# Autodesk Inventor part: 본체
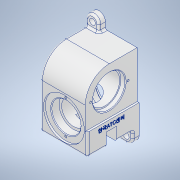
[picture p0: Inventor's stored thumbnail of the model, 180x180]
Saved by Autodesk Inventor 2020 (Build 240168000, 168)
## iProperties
Created: 2023-09
Part Number: 본체
Material: 알루미늄 6061
Document SubType Name: Modeling
Designer: oem
Density: 2.6997 g/cm^3
Appearance: 알루미늄 - 평지
Mass: 944 g
Surface Area: 630.599 cm^2
Volume: 349.669 cm^3
Author: oem
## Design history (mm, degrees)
sketch "스케치1"
  geometry: L1 (-40, 53)-(40, 53); L2 (40, 53)-(40, -53); L3 (40, -53)-(-40, -53); L4 (-40, -53)-(-40, 53); L5 (-40, 53)-(40, -53); L6 (40, 53)-(-40, -53); 1 further point
  constraints: 12 end point, 2 midpoint, 2 parallel, 1 horizontal, 1 perpendicular
  dimensions: "d0" = 80 distance of L1.start L1.end; "d1" = 106 distance of L1.end L2.end
extrude "돌출1" new body sketch "스케치1" stored distance "d2" = 72; taper "d3" = 0 deg
sketch "스케치2"
  geometry: L1 (-40, 53)-(-40, -53) reference; L2 (40, 53)-(-40, 53) reference; C1 r 37 at (-3, 16); 3 further points
  constraints: 2 tangent, 1 centre point
  dimensions: "d4" = 74 diameter of C1
extrude "돌출2" cut sketch "스케치2" stored distance "d5" = 72; taper "d6" = 0 deg
sketch "스케치3"
  geometry: L1 (72, 0)-(0, 0) reference; L2 (72, 0)-(0, 0) reference; L3 (0, -20)-(72, -20); L4 (72, -20)-(72, 0); L5 (72, 0)-(0, 0); L6 (0, 0)-(0, -20); L7 (0, -20)-(72, 0); L8 (72, -20)-(0, 0); 4 further points
  constraints: 12 end point, 3 midpoint, 2 parallel, 1 horizontal, 1 perpendicular, 1 vertical alignment
  dimensions: "d7" = 20 distance of L5.end L3.start
extrude "돌출3" join sketch "스케치3" distance "d8" = 10; taper "d9" = 0 deg
sketch "스케치4"
  geometry: L1 (72, 0)-(0, 0) reference; L2 (52, 20)-(72, 20); L3 (72, 20)-(72, 0); L4 (72, 0)-(52, 0); L5 (52, 0)-(52, 20); L6 (52, 20)-(72, 0); L7 (72, 20)-(52, 0); 3 further points
  constraints: 12 end point, 2 midpoint, 2 parallel, 1 horizontal, 1 perpendicular
  dimensions: "d11" = 20 distance of L2.end L1.start; "d12" = 20 distance of L2.start L2.end
extrude "돌출4" join sketch "스케치4" distance "d13" = 10; taper "d14" = 0 deg
sketch "스케치10"
  geometry: L1 (72, 69)-(72, 0) reference; L2 (72, 106)-(72, -20) reference; L3 (72, 106)-(69, 106); L4 (69, 106)-(69, 34); L5 (69, 34)-(72, 34); L6 (72, 34)-(72, 106); 2 further points
  constraints: 8 end point, 2 parallel, 1 horizontal, 1 perpendicular
  dimensions: "d29" = 72 distance of L3.end L4.end; "d30" = 3 distance of L2.start L3.end
extrude "돌출9" cut sketch "스케치10" stored distance "d31" = 4; taper "d32" = 0 deg
sketch "스케치11"
  geometry: C1 r 25 at (37, 35); A1 r 37 centre (37, 35) between (37, 72) and (0, 35) reference; 1 further point
  constraints: 1 centre point, 1 coincident
  dimensions: "d33" = 50 diameter of C1
extrude "돌출10" cut sketch "스케치11" distance "d34" = 7; taper "d35" = 0 deg
sketch "스케치12"
  geometry: C1 r 25 at (0, 0) reference; C2 r 23 at (0, 0); 1 further point
  constraints: 1 centre point, 1 coincident
  dimensions: "d36" = 46 diameter of C2
extrude "돌출11" cut sketch "스케치12" distance "d37" = 40; taper "d38" = 0 deg
sketch "스케치13"
  geometry: C1 r 23 at (0, 0) reference; C2 r 17.5 at (0, 0); 1 further point
  constraints: 1 centre point, 1 coincident
  dimensions: "d39" = 35 diameter of C2
extrude "돌출12" cut sketch "스케치13" distance "d40" = 15; taper "d41" = 0 deg
sketch "스케치14"
  geometry: C1 r 17.5 at (0, 0) reference; C2 r 15.5 at (0, 0); 1 further point
  constraints: 1 centre point, 1 coincident
  dimensions: "d42" = 31 diameter of C2
extrude "돌출13" cut sketch "스케치14" distance "d43" = 4; taper "d44" = 0 deg
sketch "스케치15"
  geometry: L1 (0, -20)-(72, -20) reference; C1 r 31.5 at (36, 35); 1 further point
  constraints: 1 centre point, 1 vertical alignment
  dimensions: "d45" = 55 distance from line of L1 C1.centre; "d46" = 63 diameter of C1
extrude "돌출14" cut sketch "스케치15" distance "d47" = 3; taper "d48" = 0 deg
sketch "스케치16"
  geometry: C1 r 31.5 at (0, 0) reference; C2 r 22.5 at (0, 0); 1 further point
  constraints: 1 centre point, 1 coincident
  dimensions: "d49" = 45 diameter of C2
extrude "돌출15" cut sketch "스케치16" distance "d50" = 12; taper "d51" = 0 deg
sketch "스케치17"
  geometry: C1 r 31.5 at (36, 55) reference; C2 r 22.5 at (36, 55) reference; C3 r 31.5 at (36, 55); 1 further point
  constraints: 1 centre point, 1 coincident
  dimensions: "d52" = 63 diameter of C3
extrude "돌출16" cut sketch "스케치17" distance "d53" = 8; taper "d54" = 0 deg
sketch "스케치18"
  geometry: C1 r 31.5 at (0, 0) reference; C2 r 22.5 at (0, 0); 1 further point
  constraints: 1 centre point, 1 coincident
  dimensions: "d55" = 45 diameter of C2
extrude "돌출17" cut sketch "스케치18" distance "d56" = 12; taper "d57" = 0 deg
sketch "스케치19"
  geometry: C1 r 22.5 at (0, 0) reference; C2 r 18.5 at (0, 0); 1 further point
  constraints: 1 centre point, 1 coincident
  dimensions: "d58" = 37 diameter of C2
extrude "돌출18" cut sketch "스케치19" stored distance "d59" = 12; taper "d60" = 0 deg
sketch "스케치20"
  geometry: L1 (-40, -53)-(30, -53) reference; L2 (30, -53)-(-40, -53) reference; L3 (-11, -33)-(5, -33); L4 (5, -33)-(5, -53); L5 (5, -53)-(-11, -53); L6 (-11, -53)-(-11, -33); L7 (-11, -33)-(5, -53); L8 (5, -33)-(-11, -53); 5 further points
  constraints: 12 end point, 2 midpoint, 2 parallel, 1 horizontal, 1 perpendicular, 1 point on line
  dimensions: "d61" = 43 horizontal distance of point (40, -73) point (-3, -43); "d62" = 16 distance of L3.start L3.end; "d63" = 20 distance of L5.end L3.start
extrude "돌출19" cut sketch "스케치20" stored distance "d64" = 12; taper "d65" = 0 deg
sketch "스케치21"
  geometry: L1 (-52, 20)-(-72, 20) reference; L2 (-72, 20)-(-72, 0) reference; L3 (-52, 0)-(-52, 20) reference; C1 r 10 at (-62, 10); 6 further points
  constraints: 2 midpoint, 1 centre point, 1 horizontal alignment, 1 vertical alignment
  dimensions: "d66" = 20 diameter of C1
extrude "돌출20" cut sketch "스케치21" extent not by distance; stored distance "d67" = 0; taper "d68" = 0 deg
sketch "스케치22" dims "d69" = 58
  geometry: C1 r 25 at (37, 35) reference; A1 r 37 centre (37, 35) between (37, 72) and (0, 35) reference; 3 further points
  constraints: 2 horizontal alignment, 1 coincident, 2 other
hole "구멍1" sketch "스케치22" at (8, 35) diameter "d70" = 3.242; stored, may be unused: countersink angle "d74" = 90 deg, drill point angle "d76" = 118 deg; dims "d71" = 8, "d72" = 4, "d73" = 2, "d75" = 10
fillet "모깎기1" dims "d80" = 10
sketch "스케치23"
  geometry: A1 r 10 centre (-62, -10) between (-72, -10) and (-62, -20) reference; A2 r 10 centre (-10, -10) between (-10, -20) and (0, -10) reference; 3 further points
  constraints: 2 coincident
hole "구멍2" sketch "스케치23" at (-62, -10), (-10, -10) diameter "d81" = 9; stored, may be unused: countersink angle "d85" = 90 deg, drill point angle "d87" = 118 deg; dims "d82" = 8, "d83" = 4, "d84" = 2, "d86" = 10
sketch "스케치24"
  geometry: A1 r 10 centre (-62, 10) between (-52, 10) and (-72, 10) reference; 2 further points
  constraints: 1 coincident
hole "구멍3" sketch "스케치24" at (-62, 10) diameter "d88" = 9; stored, may be unused: countersink angle "d92" = 90 deg, drill point angle "d94" = 118 deg; dims "d89" = 8, "d90" = 4, "d91" = 2, "d93" = 10
sketch "스케치25" dims "d95" = 52
  geometry: C1 r 22.5 at (0, 0) reference; C2 r 31.5 at (0, 0) reference; 3 further points
  constraints: 2 vertical alignment, 1 coincident, 2 other
hole "구멍4" sketch "스케치25" at (0, 26) diameter "d96" = 3.242; stored, may be unused: countersink angle "d100" = 90 deg, drill point angle "d102" = 118 deg; dims "d97" = 8, "d98" = 4, "d99" = 2, "d101" = 10
sketch "스케치26" dims "d106" = 52
  geometry: C1 r 22.5 at (0, 0) reference; C2 r 31.5 at (0, 0) reference; 3 further points
  constraints: 2 vertical alignment, 1 coincident, 2 other
hole "구멍5" sketch "스케치26" at (0, 26) diameter "d107" = 3.242; stored, may be unused: countersink angle "d111" = 90 deg, drill point angle "d113" = 118 deg; dims "d108" = 8, "d109" = 4, "d110" = 2, "d112" = 10
sketch "스케치27"
  geometry: L1 (0, 0)-(16, 0) reference; 4 further points
  constraints: 2 vertical alignment, 1 midpoint
  dimensions: "d117" = 50 distance of point (8, -61) point (8, -11); "d118" = 11 distance from line of point (8, -11) L1
hole "구멍6" sketch "스케치27" at (8, -11), (8, -61) diameter "d119" = 3.242; stored, may be unused: countersink angle "d123" = 90 deg, drill point angle "d125" = 118 deg; dims "d120" = 8, "d121" = 4, "d122" = 2, "d124" = 10
chamfer "모따기1" distance "d126" = 1; stored, may be unused: second distance "d127" = 2, angle "d128" = 45 deg
chamfer "모따기2" distance "d129" = 1; stored, may be unused: second distance "d130" = 2, angle "d131" = 45 deg
chamfer "모따기3" distance "d132" = 1; stored, may be unused: second distance "d133" = 2, angle "d134" = 45 deg
fillet "모깎기2" dims "d135" = 0.3
fillet "모깎기3" dims "d136" = 3
fillet "모깎기4" dims "d137" = 3
fillet "모깎기5" dims "d138" = 3
fillet "모깎기6" dims "d139" = 3
fillet "모깎기7" dims "d140" = 3
fillet "모깎기8" dims "d141" = 3
node "작업 평면1"
sketch "스케치28"
  geometry: L1 (-11, -33)-(5, -33) reference; L2 (-37, -53)-(-11, -53) reference; 3 further points
  constraints: 1 midpoint, 1 vertical alignment, 1 other
  dimensions: "d143" = 27 distance from line of L2 point (-3, -26)
feature "엠보싱1" sketch "스케치28" dims "d144" = 0.5, "d145" = 0
node "작업 평면2"
node "솔리드1"
pattern_circular "원형 패턴1" dims angle "d78" = 360 deg
pattern_circular "원형 패턴2" dims angle "d104" = 360 deg
pattern_circular "원형 패턴3" dims angle "d115" = 360 deg
feature "A9D066F2-1C7D-4E18-AEED-F7BC21143FA4" dims "d81" = 9, "d82" = 8, "d83" = 4, "d84" = 2, "d85" = 90 deg, "d86" = 10, "d87" = 118 deg
other parameters: "d142" = 45
